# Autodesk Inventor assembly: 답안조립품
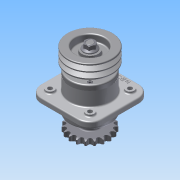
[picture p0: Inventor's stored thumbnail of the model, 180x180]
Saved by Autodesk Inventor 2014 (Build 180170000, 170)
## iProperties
Created: 2015-09
Part Number: 답안조립품
Document SubType Name: Assembly
Designer: study
Author: study
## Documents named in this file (11)
- C:\Users\study\Desktop\450909V1019\답안조립품.iam
- C:\Users\study\Desktop\450909V1019\1-본체.ipt
- C:\Users\study\Desktop\450909V1019\6-베어링 6206.ipt
- C:\Users\study\Desktop\450909V1019\3-축.ipt
- C:\Users\study\Desktop\450909V1019\2-커버.ipt
- C:\Users\study\Desktop\450909V1019\8-오일실 30x42.ipt
- C:\Users\study\Desktop\450909V1019\11-키 6x6.ipt
- C:\Users\study\Desktop\450909V1019\10-M6.ipt
- C:\Users\study\Desktop\450909V1019\4-V벨트풀리.ipt
- C:\Users\study\Desktop\450909V1019\9-M16-너트.ipt
- C:\Users\study\Desktop\450909V1019\5-체인 스프로킷.ipt
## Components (22 placed, 10 different names)
1. 1-본체:1
2. 6-베어링 6206:1
3. 6-베어링 6206:2
4. 3-축:1 — 각도:1, 각도:2
5. 2-커버:1
6. 2-커버:2
7. 8-8-오일실 30x42:1
8. 8-8-오일실 30x42:2
9. 11-키 6x6:1 — 각도:2, 각도:4
10. 11-키 6x6:2 — 각도:1, 각도:3
11. 4-V벨트풀리:1 — 각도:3, 각도:5
12. 9-M16 너트:1 — 각도:5
13. 5-체인 스프로킷:1 — 각도:4, 각도:6
14. 9-M16 너트:2 — 각도:6
15. 10-M6:2
16. 10-M6:3
17. 10-M6:4
18. 10-M6:5
19. 10-M6:1
20. 10-M6:6
21. 10-M6:7
22. 10-M6:8
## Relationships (6: Angle 6)
- 각도:1 [Angle]: 3-축:1 ↔ 11-키 6x6:2
- 각도:2 [Angle]: 3-축:1 ↔ 11-키 6x6:1
- 각도:3 [Angle]: 11-키 6x6:2 ↔ 4-V벨트풀리:1
- 각도:4 [Angle]: 11-키 6x6:1 ↔ 5-체인 스프로킷:1
- 각도:5 [Angle]: 4-V벨트풀리:1 ↔ 9-M16 너트:1
- 각도:6 [Angle]: 5-체인 스프로킷:1 ↔ 9-M16 너트:2
